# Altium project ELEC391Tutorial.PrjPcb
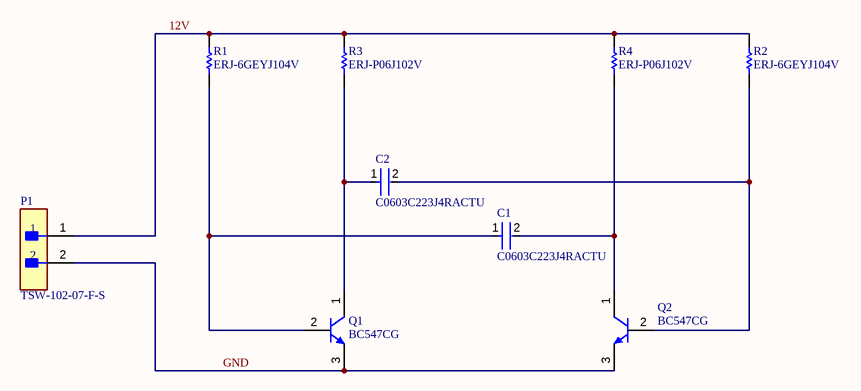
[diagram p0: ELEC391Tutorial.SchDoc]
1 sheet, 9 parts. Net scope: global (net labels, ports and power ports of the same name join across sheets).
Board file: ELEC391Tutorial.PcbDoc

## Sheet ELEC391Tutorial.SchDoc
size 431 x 279 mm; SheetNumber: 1; SheetTotal: 1; ENG_APP_DATE: --/--/--; DSN_APP_DATE: --/--/--; CHK_APP_DATE: --/--/--

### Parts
C1  C0603C223J4RACTU  [FP-C0603C-CF-MFG]
C2  C0603C223J4RACTU  [FP-C0603C-CF-MFG]
P1  TSW-102-07-F-S  [FP-TSW-102-07-F-S-MFG]
Q1  BC547CG  [ONSC-TO-92-3-29-11]
Q2  BC547CG  [ONSC-TO-92-3-29-11]
R1  ERJ-6GEYJ104V  [RESC2013X70X40NL20T20]
R2  ERJ-6GEYJ104V  [RESC2013X70X40NL20T20]
R3  ERJ-P06J102V  [RESC2013X70X40LL20T20]
R4  ERJ-P06J102V  [RESC2013X70X40LL20T20]

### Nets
12V: P1.1 R1.2 R2.2 R3.2 R4.2
GND: P1.2 Q1.3(E) Q2.3(E)
NetC1_1: C1.1 Q1.2(B) R1.1
NetC1_2: C1.2 Q2.1(C) R4.1
NetC2_1: C2.1 Q1.1(C) R3.1
NetC2_2: C2.2 Q2.2(B) R2.1

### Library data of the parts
C1 C2 = CMP-2006-03745-2: CAP CER 0.022UF 16V 5% X7R 0603; Manufacturer: KEMET; Tolerance: 0.05; Automotive Grade: Grade 1; Temperature Coefficient: 30ppm/°C; Description: C0603 22,000 pF X7R 30ppm/°C 5.00% 16 V; Capacitance: 22,000 pF; Material: Ceramic; Value: 22,000 pF
P1 = CMP-002-00071-1: Board Connector, 2 Contact(s), 1 Row(s), Male, Straight, 0.1 inch Pitch, Solder Terminal, Black Insulator
Q1 Q2 = CMP-1048-01464-1: Amplifier Transistor, NPN Silicon, 3-Pin TO-92, Pb-Free, Bulk Box; Manufacturer: On Semiconductor; IC Continuous (A): 0.1; fT Min (MHz): 150
R1 R2 = CMP-2001-00338-1: Manufacturer: Panasonic
R3 R4 = CMP-2001-00477-1: Manufacturer: Panasonic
